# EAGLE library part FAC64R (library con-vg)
CONNECTOR female, 64 pins, type R, rows AC, grid 5.08 mm
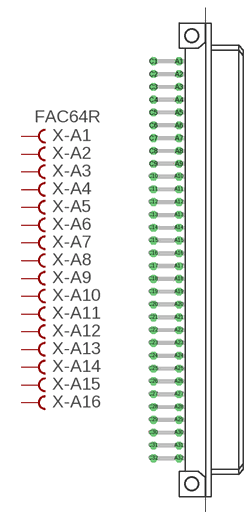
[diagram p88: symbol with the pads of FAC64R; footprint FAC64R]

Designator prefix X; gates -A1=FVAL -A2=FEM -A3=FEM -A4=FEM -A5=FEM -A6=FEM -A7=FEM -A8=FEM -A9=FEM -A10=FEM -A11=FEM -A12=FEM -A13=FEM -A14=FEM -A15=FEM -A16=FEM -A17=FEM -A18=FEM -A19=FEM -A20=FEM -A21=FEM -A22=FEM -A23=FEM -A24=FEM -A25=FEM -A26=FEM -A27=FEM -A28=FEM -A29=FEM -A30=FEM -A31=FEM -A32=FEM -C1=FVAL -C2=FEM -C3=FEM -C4=FEM -C5=FEM -C6=FEM -C7=FEM -C8=FEM -C9=FEM -C10=FEM -C11=FEM -C12=FEM -C13=FEM -C14=FEM -C15=FEM -C16=FEM -C17=FEM -C18=FEM -C19=FEM -C20=FEM -C21=FEM -C22=FEM -C23=FEM -C24=FEM -C25=FEM -C26=FEM -C27=FEM -C28=FEM -C29=FEM -C30=FEM -C31=FEM -C32=FEM

## FAC64R  [FAC64R]
A1  -A1:B  pas
A2  -A2:B  pas
A3  -A3:B  pas
A4  -A4:B  pas
A5  -A5:B  pas
A6  -A6:B  pas
A7  -A7:B  pas
A8  -A8:B  pas
A9  -A9:B  pas
A10  -A10:B  pas
A11  -A11:B  pas
A12  -A12:B  pas
A13  -A13:B  pas
A14  -A14:B  pas
A15  -A15:B  pas
A16  -A16:B  pas
A17  -A17:B  pas
A18  -A18:B  pas
A19  -A19:B  pas
A20  -A20:B  pas
A21  -A21:B  pas
A22  -A22:B  pas
A23  -A23:B  pas
A24  -A24:B  pas
A25  -A25:B  pas
A26  -A26:B  pas
A27  -A27:B  pas
A28  -A28:B  pas
A29  -A29:B  pas
A30  -A30:B  pas
A31  -A31:B  pas
A32  -A32:B  pas
C1  -C1:B  pas
C2  -C2:B  pas
C3  -C3:B  pas
C4  -C4:B  pas
C5  -C5:B  pas
C6  -C6:B  pas
C7  -C7:B  pas
C8  -C8:B  pas
C9  -C9:B  pas
C10  -C10:B  pas
C11  -C11:B  pas
C12  -C12:B  pas
C13  -C13:B  pas
C14  -C14:B  pas
C15  -C15:B  pas
C16  -C16:B  pas
C17  -C17:B  pas
C18  -C18:B  pas
C19  -C19:B  pas
C20  -C20:B  pas
C21  -C21:B  pas
C22  -C22:B  pas
C23  -C23:B  pas
C24  -C24:B  pas
C25  -C25:B  pas
C26  -C26:B  pas
C27  -C27:B  pas
C28  -C28:B  pas
C29  -C29:B  pas
C30  -C30:B  pas
C31  -C31:B  pas
C32  -C32:B  pas

## Footprint FAC64R (pad centres in mm)
CONNECTOR female, 64 pins, type R, rows AC, grid 5.08 mm
drill 1.016 octagon: A1 -2.54,39.37; A2 -2.54,36.83; A3 -2.54,34.29; A4 -2.54,31.75; A5 -2.54,29.21; A6 -2.54,26.67; A7 -2.54,24.13; A8 -2.54,21.59; A9 -2.54,19.05; A10 -2.54,16.51; A11 -2.54,13.97; A12 -2.54,11.43; A13 -2.54,8.89; A14 -2.54,6.35; A15 -2.54,3.81; A16 -2.54,1.27; A17 -2.54,-1.27; A18 -2.54,-3.81; A19 -2.54,-6.35; A20 -2.54,-8.89; A21 -2.54,-11.43; A22 -2.54,-13.97; A23 -2.54,-16.51; A24 -2.54,-19.05; A25 -2.54,-21.59; A26 -2.54,-24.13; A27 -2.54,-26.67; A28 -2.54,-29.21; A29 -2.54,-31.75; A30 -2.54,-34.29; A31 -2.54,-36.83; A32 -2.54,-39.37; C1 -7.62,39.37; C2 -7.62,36.83; C3 -7.62,34.29; C4 -7.62,31.75; C5 -7.62,29.21; C6 -7.62,26.67; C7 -7.62,24.13; C8 -7.62,21.59; C9 -7.62,19.05; C10 -7.62,16.51; C11 -7.62,13.97; C12 -7.62,11.43; C13 -7.62,8.89; C14 -7.62,6.35; C15 -7.62,3.81; C16 -7.62,1.27; C17 -7.62,-1.27; C18 -7.62,-3.81; C19 -7.62,-6.35; C20 -7.62,-8.89; C21 -7.62,-11.43; C22 -7.62,-13.97; C23 -7.62,-16.51; C24 -7.62,-19.05; C25 -7.62,-21.59; C26 -7.62,-24.13; C27 -7.62,-26.67; C28 -7.62,-29.21; C29 -7.62,-31.75; C30 -7.62,-34.29; C31 -7.62,-36.83; C32 -7.62,-39.37
hole 2.794 at 0,-44.456
hole 2.794 at 0,44.456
